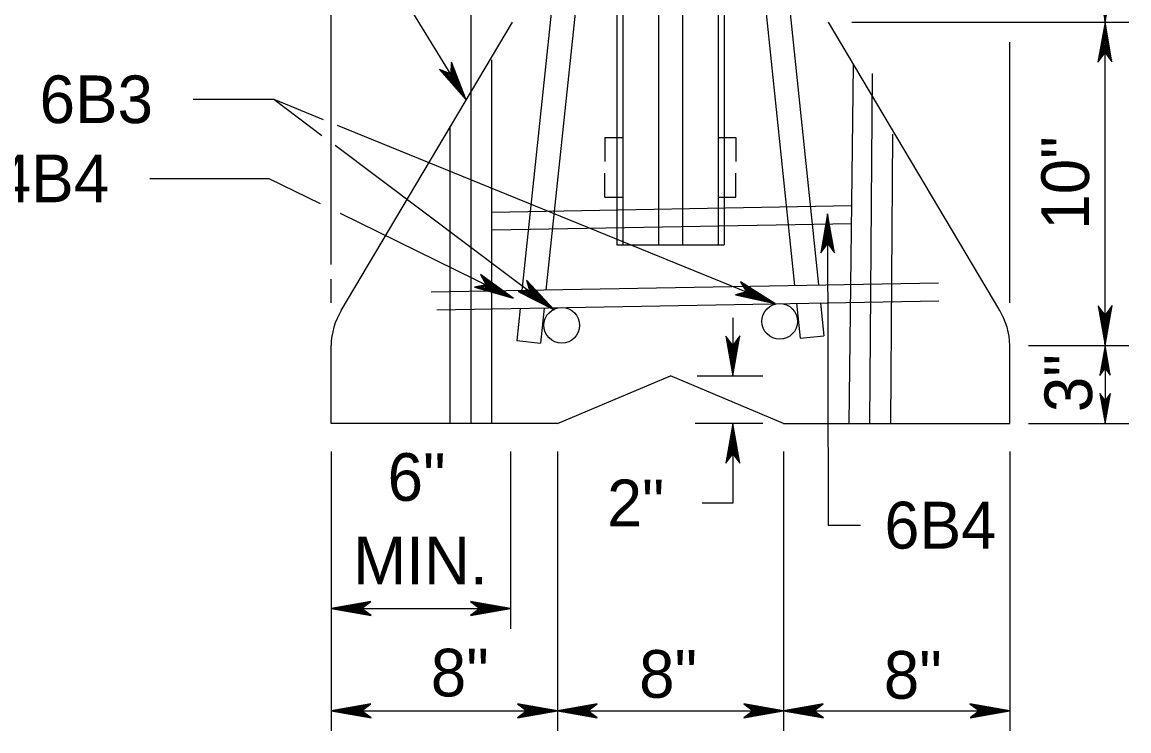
# Model space of a CAD drawing. Extents: x 499866 to 500993, y 499985 to 500645.
# Drawn here: x 500319.6 to 500412.5, y 500301 to 500360.4 of the extents above; entities that cross this region are included whole.
import ezdxf

# ---------------------------------------------------------------- set-up
doc = ezdxf.new("R2010")
doc.units = 0
for name, color, linetype in [('24', 7, 'Continuous'), ('5', 7, 'Continuous'), ('60', 7, 'Continuous')]:
    doc.layers.add(name, color=color, linetype=linetype)

msp = doc.modelspace()

# ---------------------------------------------------------------- linework, layer by layer
at = {"layer": '24'}
for points in [[(500409.949, 500363.769), (500410.532, 500360.436), (500410.527, 500360.658)], [(500410.532, 500360.436), (500411.125, 500363.786)], [(500410.532, 500360.436), (500409.94, 500357.086), (500410.532, 500357.886), (500411.115, 500357.103), (500410.532, 500360.436), (500410.538, 500360.214), (500409.984, 500357.18), (500410.54, 500357.949), (500411.07, 500357.239), (500410.549, 500360.094), (500410.532, 500359.982), (500410.071, 500357.383), (500410.539, 500357.966), (500410.994, 500357.367), (500410.532, 500359.931), (500410.549, 500359.82), (500410.139, 500357.548), (500410.532, 500357.99), (500410.941, 500357.539), (500410.55, 500359.496), (500410.549, 500359.307), (500410.223, 500357.717), (500410.523, 500358.026), (500410.856, 500357.693), (500410.532, 500359.273), (500410.522, 500359.094), (500410.317, 500357.899), (500410.55, 500358.129), (500410.779, 500357.879), (500410.532, 500358.93), (500410.515, 500358.761), (500410.378, 500358.043), (500410.54, 500358.161), (500410.719, 500357.966), (500410.532, 500358.674), (500410.421, 500358.205), (500410.549, 500358.273), (500410.677, 500358.068), (500410.55, 500358.556), (500410.472, 500358.249), (500410.573, 500358.378), (500410.634, 500358.23), (500410.54, 500358.377), (500410.523, 500358.3)], [(500356.927, 500353.917), (500355.679, 500357.082), (500355.594, 500356.09), (500354.687, 500356.452), (500356.927, 500353.917), (500356.805, 500354.103), (500355.691, 500356.979), (500355.62, 500356.033), (500354.797, 500356.361), (500356.734, 500354.2), (500356.689, 500354.304), (500355.724, 500356.76), (500355.629, 500356.018), (500354.928, 500356.291), (500356.663, 500354.347), (500356.591, 500354.433), (500355.752, 500356.584), (500355.648, 500356.002), (500355.063, 500356.173), (500356.421, 500354.709), (500356.323, 500354.87), (500355.768, 500356.396), (500355.675, 500355.976), (500355.216, 500356.086), (500356.319, 500354.908), (500356.234, 500355.066), (500355.783, 500356.192), (500355.705, 500355.874), (500355.38, 500355.967), (500356.139, 500355.2), (500356.066, 500355.353), (500355.807, 500356.037), (500355.731, 500355.852), (500355.476, 500355.925), (500356.006, 500355.419), (500355.855, 500355.876), (500355.782, 500355.751), (500355.565, 500355.86), (500355.929, 500355.51), (500355.834, 500355.812), (500355.815, 500355.65), (500355.686, 500355.744), (500355.844, 500355.668), (500355.818, 500355.742)], [(500387.251, 500344.346), (500386.678, 500341.071), (500387.256, 500341.854), (500387.827, 500341.09), (500387.251, 500344.346), (500387.257, 500344.129), (500386.721, 500341.163), (500387.263, 500341.915), (500387.782, 500341.222), (500387.267, 500344.011), (500387.251, 500343.903), (500386.805, 500341.362), (500387.262, 500341.932), (500387.708, 500341.347), (500387.251, 500343.852), (500387.268, 500343.744), (500386.872, 500341.523), (500387.255, 500341.956), (500387.656, 500341.515), (500387.269, 500343.428), (500387.269, 500343.243), (500386.954, 500341.688), (500387.246, 500341.991), (500387.572, 500341.666), (500387.253, 500343.21), (500387.243, 500343.035), (500387.045, 500341.866), (500387.272, 500342.091), (500387.496, 500341.848), (500387.254, 500342.875), (500387.238, 500342.71), (500387.104, 500342.007), (500387.262, 500342.123), (500387.438, 500341.932), (500387.254, 500342.624), (500387.146, 500342.166), (500387.271, 500342.232), (500387.397, 500342.032), (500387.271, 500342.509), (500387.196, 500342.208), (500387.295, 500342.334), (500387.354, 500342.19), (500387.262, 500342.334), (500387.245, 500342.259)], [(500387.251, 500344.346), (500387.305, 500318.223), (500390.021, 500318.223)], [(500360.871, 500337.262), (500358.124, 500339.269), (500358.582, 500338.385), (500357.622, 500338.207), (500360.871, 500337.262), (500360.668, 500337.355), (500358.189, 500339.189), (500358.635, 500338.351), (500357.763, 500338.188), (500360.556, 500337.399), (500360.463, 500337.462), (500358.333, 500339.022), (500358.65, 500338.344), (500357.912, 500338.199), (500360.417, 500337.485), (500360.31, 500337.519), (500358.451, 500338.888), (500358.675, 500338.34), (500358.09, 500338.172), (500360.019, 500337.661), (500359.85, 500337.745), (500358.565, 500338.738), (500358.711, 500338.332), (500358.265, 500338.18), (500359.827, 500337.775), (500359.671, 500337.863), (500358.687, 500338.573), (500358.792, 500338.263), (500358.467, 500338.167), (500359.519, 500337.926), (500359.375, 500338.015), (500358.79, 500338.455), (500358.825, 500338.258), (500358.571, 500338.183), (500359.289, 500338.039), (500358.917, 500338.345), (500358.922, 500338.2), (500358.68, 500338.175), (500359.176, 500338.075), (500358.933, 500338.28), (500359.005, 500338.132), (500358.845, 500338.143), (500359.019, 500338.163), (500358.957, 500338.212)], [(500364.296, 500336.299), (500361.973, 500338.784), (500362.258, 500337.83), (500361.281, 500337.834), (500364.296, 500336.299), (500364.115, 500336.428), (500362.022, 500338.693), (500362.303, 500337.787), (500361.417, 500337.79), (500364.012, 500336.491), (500363.933, 500336.572), (500362.133, 500338.502), (500362.317, 500337.777), (500361.565, 500337.773), (500363.892, 500336.603), (500363.794, 500336.656), (500362.223, 500338.348), (500362.341, 500337.768), (500361.734, 500337.713), (500363.534, 500336.85), (500363.384, 500336.964), (500362.307, 500338.179), (500362.375, 500337.754), (500361.908, 500337.688), (500363.366, 500336.997), (500363.23, 500337.113), (500362.397, 500337.995), (500362.441, 500337.671), (500362.104, 500337.638), (500363.092, 500337.203), (500362.968, 500337.318), (500362.475, 500337.86), (500362.473, 500337.659), (500362.21, 500337.634), (500362.887, 500337.358), (500362.58, 500337.728), (500362.557, 500337.585), (500362.316, 500337.605), (500362.783, 500337.414), (500362.583, 500337.661), (500362.626, 500337.502), (500362.471, 500337.543), (500362.645, 500337.53), (500362.594, 500337.59)], [(500382.815, 500336.834), (500379.936, 500338.647), (500380.454, 500337.796), (500379.508, 500337.552), (500382.815, 500336.834), (500382.606, 500336.912), (500380.006, 500338.571), (500380.509, 500337.766), (500379.651, 500337.543), (500382.491, 500336.948), (500382.394, 500337.005), (500380.162, 500338.414), (500380.525, 500337.76), (500379.798, 500337.565), (500382.347, 500337.025), (500382.238, 500337.052), (500380.289, 500338.288), (500380.55, 500337.758), (500379.977, 500337.549), (500381.938, 500337.173), (500381.763, 500337.245), (500380.413, 500338.146), (500380.586, 500337.752), (500380.152, 500337.57), (500381.738, 500337.273), (500381.576, 500337.35), (500380.546, 500337.991), (500380.671, 500337.689), (500380.354, 500337.571), (500381.42, 500337.402), (500381.27, 500337.482), (500380.657, 500337.88), (500380.705, 500337.686), (500380.457, 500337.594), (500381.183, 500337.499), (500380.791, 500337.779), (500380.806, 500337.635), (500380.567, 500337.594), (500381.067, 500337.528), (500380.812, 500337.715), (500380.893, 500337.573), (500380.733, 500337.573), (500380.905, 500337.604), (500380.84, 500337.649)], [(500410.532, 500333.301), (500411.125, 500336.651), (500410.532, 500335.851), (500409.949, 500336.634), (500410.532, 500333.301), (500410.527, 500333.524), (500411.081, 500336.557), (500410.525, 500335.788), (500409.995, 500336.499), (500410.516, 500333.644), (500410.532, 500333.755), (500410.994, 500336.354), (500410.526, 500335.771), (500410.071, 500336.37), (500410.533, 500333.806), (500410.516, 500333.918), (500410.926, 500336.189), (500410.533, 500335.747), (500410.124, 500336.198), (500410.515, 500334.241), (500410.516, 500334.43), (500410.842, 500336.021), (500410.542, 500335.711), (500410.209, 500336.045), (500410.532, 500334.464), (500410.543, 500334.643), (500410.748, 500335.839), (500410.515, 500335.609), (500410.286, 500335.858), (500410.532, 500334.807), (500410.55, 500334.976), (500410.687, 500335.694), (500410.525, 500335.576), (500410.346, 500335.771), (500410.533, 500335.063), (500410.644, 500335.532), (500410.516, 500335.464), (500410.387, 500335.67), (500410.515, 500335.181), (500410.593, 500335.489), (500410.491, 500335.36), (500410.431, 500335.508), (500410.525, 500335.361), (500410.542, 500335.437)], [(500379.299, 500330.762), (500379.891, 500334.113), (500379.299, 500333.312), (500378.716, 500334.095), (500379.299, 500330.762), (500379.293, 500330.985), (500379.847, 500334.019), (500379.292, 500333.25), (500378.762, 500333.96), (500379.283, 500331.105), (500379.299, 500331.217), (500379.761, 500333.815), (500379.292, 500333.232), (500378.838, 500333.832), (500379.3, 500331.268), (500379.283, 500331.379), (500379.693, 500333.651), (500379.3, 500333.209), (500378.891, 500333.66), (500379.282, 500331.702), (500379.283, 500331.891), (500379.608, 500333.482), (500379.309, 500333.173), (500378.976, 500333.506), (500379.299, 500331.925), (500379.31, 500332.104), (500379.514, 500333.3), (500379.282, 500333.07), (500379.053, 500333.319), (500379.299, 500332.268), (500379.316, 500332.437), (500379.453, 500333.156), (500379.292, 500333.037), (500379.113, 500333.233), (500379.3, 500332.525), (500379.411, 500332.993), (500379.283, 500332.925), (500379.154, 500333.131), (500379.282, 500332.642), (500379.359, 500332.95), (500379.258, 500332.821), (500379.198, 500332.969), (500379.292, 500332.822), (500379.309, 500332.899)], [(500410.532, 500333.301), (500410.088, 500330.789), (500410.532, 500331.389), (500410.97, 500330.802), (500410.532, 500333.301), (500410.537, 500333.135), (500410.121, 500330.859), (500410.538, 500331.436), (500410.935, 500330.903), (500410.545, 500333.044), (500410.532, 500332.961), (500410.186, 500331.011), (500410.538, 500331.449), (500410.879, 500330.999), (500410.532, 500332.922), (500410.545, 500332.839), (500410.237, 500331.135), (500410.532, 500331.467), (500410.839, 500331.128), (500410.545, 500332.596), (500410.545, 500332.454), (500410.301, 500331.261), (500410.525, 500331.493), (500410.775, 500331.243), (500410.532, 500332.429), (500410.525, 500332.295), (500410.371, 500331.398), (500410.545, 500331.571), (500410.717, 500331.384), (500410.532, 500332.172), (500410.52, 500332.045), (500410.417, 500331.507), (500410.538, 500331.595), (500410.672, 500331.448), (500410.532, 500331.98), (500410.449, 500331.628), (500410.545, 500331.679), (500410.641, 500331.525), (500410.545, 500331.891), (500410.488, 500331.661), (500410.563, 500331.757), (500410.609, 500331.646), (500410.538, 500331.757), (500410.525, 500331.699)], [(500410.532, 500326.765), (500410.977, 500329.278), (500410.532, 500328.677), (500410.095, 500329.265), (500410.532, 500326.765), (500410.528, 500326.932), (500410.944, 500329.208), (500410.527, 500328.631), (500410.13, 500329.163), (500410.52, 500327.022), (500410.532, 500327.106), (500410.879, 500329.055), (500410.527, 500328.618), (500410.186, 500329.067), (500410.533, 500327.144), (500410.52, 500327.228), (500410.828, 500328.931), (500410.533, 500328.6), (500410.226, 500328.938), (500410.52, 500327.47), (500410.52, 500327.612), (500410.764, 500328.805), (500410.54, 500328.573), (500410.29, 500328.823), (500410.532, 500327.637), (500410.54, 500327.772), (500410.694, 500328.669), (500410.52, 500328.496), (500410.348, 500328.683), (500410.532, 500327.895), (500410.545, 500328.021), (500410.648, 500328.56), (500410.527, 500328.471), (500410.393, 500328.618), (500410.533, 500328.087), (500410.616, 500328.438), (500410.52, 500328.387), (500410.424, 500328.542), (500410.52, 500328.175), (500410.577, 500328.406), (500410.502, 500328.309), (500410.456, 500328.42), (500410.527, 500328.31), (500410.54, 500328.367)], [(500379.299, 500326.765), (500378.707, 500323.415), (500379.299, 500324.216), (500379.882, 500323.433), (500379.299, 500326.765), (500379.305, 500326.543), (500378.751, 500323.509), (500379.306, 500324.278), (500379.836, 500323.568), (500379.316, 500326.423), (500379.299, 500326.311), (500378.837, 500323.713), (500379.306, 500324.296), (500379.761, 500323.696), (500379.299, 500326.26), (500379.316, 500326.149), (500378.906, 500323.877), (500379.299, 500324.319), (500379.708, 500323.868), (500379.316, 500325.825), (500379.316, 500325.636), (500378.99, 500324.046), (500379.29, 500324.355), (500379.623, 500324.022), (500379.299, 500325.603), (500379.289, 500325.424), (500379.084, 500324.228), (500379.316, 500324.458), (500379.545, 500324.209), (500379.299, 500325.26), (500379.282, 500325.091), (500379.145, 500324.372), (500379.306, 500324.491), (500379.485, 500324.295), (500379.299, 500325.003), (500379.188, 500324.535), (500379.316, 500324.603), (500379.444, 500324.397), (500379.316, 500324.885), (500379.239, 500324.578), (500379.34, 500324.707), (500379.401, 500324.559), (500379.306, 500324.706), (500379.29, 500324.629)], [(500345.582, 500311.227), (500348.932, 500310.635), (500348.132, 500311.227), (500348.915, 500311.81), (500345.582, 500311.227), (500345.804, 500311.233), (500348.838, 500310.679), (500348.069, 500311.234), (500348.78, 500311.764), (500345.925, 500311.243), (500346.036, 500311.227), (500348.635, 500310.765), (500348.052, 500311.234), (500348.651, 500311.689), (500346.087, 500311.227), (500346.198, 500311.243), (500348.47, 500310.833), (500348.028, 500311.227), (500348.479, 500311.635), (500346.522, 500311.244), (500346.711, 500311.243), (500348.302, 500310.918), (500347.992, 500311.218), (500348.325, 500311.551), (500346.745, 500311.227), (500346.924, 500311.217), (500348.119, 500311.012), (500347.889, 500311.244), (500348.139, 500311.473), (500347.088, 500311.227), (500347.257, 500311.21), (500347.975, 500311.073), (500347.857, 500311.234), (500348.052, 500311.413), (500347.344, 500311.227), (500347.813, 500311.115), (500347.745, 500311.243), (500347.95, 500311.372), (500347.462, 500311.244), (500347.769, 500311.167), (500347.64, 500311.268), (500347.788, 500311.328), (500347.641, 500311.234), (500347.718, 500311.218)], [(500360.621, 500311.227), (500357.271, 500311.819), (500358.072, 500311.227), (500357.289, 500310.644), (500360.621, 500311.227), (500360.399, 500311.221), (500357.365, 500311.775), (500358.134, 500311.22), (500357.424, 500310.69), (500360.279, 500311.211), (500360.167, 500311.227), (500357.569, 500311.689), (500358.152, 500311.22), (500357.552, 500310.765), (500360.116, 500311.227), (500360.005, 500311.211), (500357.733, 500311.621), (500358.175, 500311.227), (500357.724, 500310.819), (500359.681, 500311.21), (500359.492, 500311.211), (500357.902, 500311.536), (500358.211, 500311.237), (500357.878, 500310.904), (500359.459, 500311.227), (500359.28, 500311.238), (500358.084, 500311.442), (500358.314, 500311.21), (500358.065, 500310.981), (500359.115, 500311.227), (500358.947, 500311.244), (500358.228, 500311.381), (500358.347, 500311.22), (500358.151, 500311.041), (500358.859, 500311.227), (500358.391, 500311.339), (500358.459, 500311.211), (500358.253, 500311.082), (500358.741, 500311.21), (500358.434, 500311.287), (500358.563, 500311.186), (500358.415, 500311.126), (500358.562, 500311.22), (500358.485, 500311.237)], [(500345.582, 500302.645), (500348.932, 500302.053), (500348.132, 500302.645), (500348.915, 500303.228), (500345.582, 500302.645), (500345.804, 500302.651), (500348.838, 500302.097), (500348.069, 500302.652), (500348.78, 500303.182), (500345.925, 500302.661), (500346.036, 500302.645), (500348.635, 500302.183), (500348.052, 500302.652), (500348.651, 500303.107), (500346.087, 500302.645), (500346.198, 500302.661), (500348.47, 500302.251), (500348.028, 500302.645), (500348.479, 500303.053), (500346.522, 500302.662), (500346.711, 500302.661), (500348.302, 500302.336), (500347.992, 500302.635), (500348.325, 500302.969), (500346.745, 500302.645), (500346.924, 500302.635), (500348.119, 500302.43), (500347.889, 500302.662), (500348.139, 500302.891), (500347.088, 500302.645), (500347.257, 500302.628), (500347.975, 500302.491), (500347.857, 500302.652), (500348.052, 500302.831), (500347.344, 500302.645), (500347.813, 500302.533), (500347.745, 500302.661), (500347.95, 500302.79), (500347.462, 500302.662), (500347.769, 500302.585), (500347.64, 500302.686), (500347.788, 500302.746), (500347.641, 500302.652), (500347.718, 500302.635)], [(500364.568, 500302.645), (500361.218, 500303.237), (500362.018, 500302.645), (500361.235, 500302.062), (500364.568, 500302.645), (500364.345, 500302.639), (500361.311, 500303.193), (500362.08, 500302.638), (500361.37, 500302.108), (500364.225, 500302.629), (500364.114, 500302.645), (500361.515, 500303.107), (500362.098, 500302.638), (500361.498, 500302.183), (500364.062, 500302.645), (500363.951, 500302.629), (500361.679, 500303.039), (500362.121, 500302.645), (500361.67, 500302.237), (500363.628, 500302.628), (500363.439, 500302.629), (500361.848, 500302.954), (500362.157, 500302.655), (500361.824, 500302.322), (500363.405, 500302.645), (500363.226, 500302.656), (500362.03, 500302.86), (500362.26, 500302.628), (500362.011, 500302.399), (500363.062, 500302.645), (500362.893, 500302.662), (500362.175, 500302.799), (500362.293, 500302.638), (500362.097, 500302.459), (500362.805, 500302.645), (500362.337, 500302.757), (500362.405, 500302.629), (500362.199, 500302.5), (500362.688, 500302.628), (500362.38, 500302.705), (500362.509, 500302.604), (500362.361, 500302.544), (500362.508, 500302.638), (500362.431, 500302.655)], [(500364.568, 500302.645), (500367.918, 500302.053), (500367.117, 500302.645), (500367.9, 500303.228), (500364.568, 500302.645), (500364.79, 500302.651), (500367.824, 500302.097), (500367.055, 500302.652), (500367.765, 500303.182), (500364.91, 500302.661), (500365.022, 500302.645), (500367.62, 500302.183), (500367.037, 500302.652), (500367.637, 500303.107), (500365.073, 500302.645), (500365.184, 500302.661), (500367.456, 500302.251), (500367.014, 500302.645), (500367.465, 500303.053), (500365.508, 500302.662), (500365.697, 500302.661), (500367.287, 500302.336), (500366.978, 500302.635), (500367.311, 500302.969), (500365.73, 500302.645), (500365.909, 500302.635), (500367.105, 500302.43), (500366.875, 500302.662), (500367.124, 500302.891), (500366.073, 500302.645), (500366.242, 500302.628), (500366.961, 500302.491), (500366.842, 500302.652), (500367.038, 500302.831), (500366.33, 500302.645), (500366.798, 500302.533), (500366.73, 500302.661), (500366.936, 500302.79), (500366.448, 500302.662), (500366.755, 500302.585), (500366.626, 500302.686), (500366.774, 500302.746), (500366.627, 500302.652), (500366.704, 500302.635)], [(500383.553, 500302.645), (500380.203, 500303.237), (500381.003, 500302.645), (500380.22, 500302.062), (500383.553, 500302.645), (500383.33, 500302.639), (500380.297, 500303.193), (500381.066, 500302.638), (500380.355, 500302.108), (500383.21, 500302.629), (500383.099, 500302.645), (500380.5, 500303.107), (500381.083, 500302.638), (500380.484, 500302.183), (500383.048, 500302.645), (500382.936, 500302.629), (500380.665, 500303.039), (500381.107, 500302.645), (500380.656, 500302.237), (500382.613, 500302.628), (500382.424, 500302.629), (500380.833, 500302.954), (500381.143, 500302.655), (500380.809, 500302.322), (500382.39, 500302.645), (500382.211, 500302.656), (500381.015, 500302.86), (500381.245, 500302.628), (500380.996, 500302.399), (500382.047, 500302.645), (500381.878, 500302.662), (500381.16, 500302.799), (500381.278, 500302.638), (500381.083, 500302.459), (500381.791, 500302.645), (500381.322, 500302.757), (500381.39, 500302.629), (500381.184, 500302.5), (500381.673, 500302.628), (500381.365, 500302.705), (500381.494, 500302.604), (500381.346, 500302.544), (500381.493, 500302.638), (500381.417, 500302.655)], [(500383.553, 500302.645), (500386.903, 500302.053), (500386.102, 500302.645), (500386.885, 500303.228), (500383.553, 500302.645), (500383.775, 500302.651), (500386.809, 500302.097), (500386.04, 500302.652), (500386.75, 500303.182), (500383.895, 500302.661), (500384.007, 500302.645), (500386.606, 500302.183), (500386.023, 500302.652), (500386.622, 500303.107), (500384.058, 500302.645), (500384.169, 500302.661), (500386.441, 500302.251), (500385.999, 500302.645), (500386.45, 500303.053), (500384.493, 500302.662), (500384.682, 500302.661), (500386.272, 500302.336), (500385.963, 500302.635), (500386.296, 500302.969), (500384.716, 500302.645), (500384.894, 500302.635), (500386.09, 500302.43), (500385.86, 500302.662), (500386.11, 500302.891), (500385.059, 500302.645), (500385.227, 500302.628), (500385.946, 500302.491), (500385.827, 500302.652), (500386.023, 500302.831), (500385.315, 500302.645), (500385.783, 500302.533), (500385.716, 500302.661), (500385.921, 500302.79), (500385.433, 500302.662), (500385.74, 500302.585), (500385.611, 500302.686), (500385.759, 500302.746), (500385.612, 500302.652), (500385.689, 500302.635)], [(500402.539, 500302.645), (500399.189, 500303.237), (500399.989, 500302.645), (500399.206, 500302.062), (500402.539, 500302.645), (500402.316, 500302.639), (500399.282, 500303.193), (500400.052, 500302.638), (500399.341, 500302.108), (500402.196, 500302.629), (500402.085, 500302.645), (500399.486, 500303.107), (500400.069, 500302.638), (500399.469, 500302.183), (500402.033, 500302.645), (500401.922, 500302.629), (500399.651, 500303.039), (500400.093, 500302.645), (500399.641, 500302.237), (500401.599, 500302.628), (500401.41, 500302.629), (500399.819, 500302.954), (500400.129, 500302.655), (500399.795, 500302.322), (500401.376, 500302.645), (500401.197, 500302.656), (500400.001, 500302.86), (500400.231, 500302.628), (500399.982, 500302.399), (500401.033, 500302.645), (500400.864, 500302.662), (500400.146, 500302.799), (500400.264, 500302.638), (500400.069, 500302.459), (500400.777, 500302.645), (500400.308, 500302.757), (500400.376, 500302.629), (500400.17, 500302.5), (500400.659, 500302.628), (500400.351, 500302.705), (500400.48, 500302.604), (500400.332, 500302.544), (500400.479, 500302.638), (500400.403, 500302.655)]]:
    msp.add_lwpolyline(points, dxfattribs=at)
at = {"layer": '5'}
for p, q in [((500410.532, 500360.436), (500410.532, 500408.703)), ((500367.837, 500397.193), (500361.595, 500337.912)), ((500380.327, 500397.193), (500386.48, 500338.379)), ((500378.371, 500396.902), (500384.478, 500338.327)), ((500370.063, 500391.629), (500370.063, 500341.754)), ((500373.061, 500391.629), (500373.061, 500341.754)), ((500375.06, 500391.66), (500375.06, 500341.754)), ((500378.057, 500391.66), (500378.057, 500341.754)), ((500378.557, 500391.66), (500378.557, 500341.754)), ((500368.189, 500381.281), (500363.607, 500337.933)), ((500369.564, 500380.588), (500369.564, 500341.754)), ((500357.323, 500326.765), (500357.323, 500379.722)), ((500345.582, 500340.097), (500345.582, 500368.682)), ((500346.432, 500336.241), (500360.798, 500360.436)), ((500401.688, 500336.241), (500387.323, 500360.436)), ((500389.288, 500360.436), (500412.531, 500360.436)), ((500410.532, 500333.301), (500410.532, 500360.436)), ((500402.539, 500336.88), (500402.539, 500358.744)), ((500359.072, 500326.765), (500359.072, 500357.272)), ((500389.049, 500326.765), (500389.434, 500356.858)), ((500390.797, 500326.779), (500391.015, 500356.133)), ((500340.783, 500353.961), (500344.811, 500350.936)), ((500346.1, 500351.795), (500382.815, 500336.834)), ((500355.574, 500326.765), (500355.574, 500351.702)), ((500368.564, 500350.747), (500368.564, 500348.749)), ((500368.564, 500350.747), (500370.063, 500350.747)), ((500378.057, 500350.747), (500379.556, 500350.747)), ((500379.556, 500350.747), (500379.556, 500348.749)), ((500392.546, 500326.765), (500392.726, 500351.043)), ((500345.914, 500350.107), (500364.296, 500336.299)), ((500368.564, 500345.751), (500368.564, 500347.749)), ((500379.556, 500345.751), (500379.556, 500347.749)), ((500368.564, 500345.751), (500370.063, 500345.751)), ((500378.057, 500345.751), (500379.556, 500345.751)), ((500346.335, 500344.392), (500360.871, 500337.262)), ((500359.072, 500344.503), (500389.261, 500345.039)), ((500359.098, 500343.005), (500389.288, 500343.54)), ((500369.564, 500341.754), (500378.557, 500341.754)), ((500345.582, 500336.88), (500345.582, 500338.88)), ((500353.985, 500337.797), (500396.558, 500338.553)), ((500354.445, 500336.306), (500396.585, 500337.054)), ((500384.633, 500336.839), (500384.939, 500333.905)), ((500386.639, 500336.864), (500386.927, 500334.113)), ((500361.436, 500336.397), (500361.153, 500333.712)), ((500363.448, 500336.423), (500363.139, 500333.502)), ((500379.299, 500335.619), (500379.299, 500330.762)), ((500384.939, 500333.905), (500386.927, 500334.113)), ((500345.582, 500326.765), (500345.582, 500333.301)), ((500361.152, 500333.712), (500363.139, 500333.502)), ((500402.539, 500326.765), (500402.539, 500333.301)), ((500404.12, 500333.301), (500412.531, 500333.301)), ((500410.532, 500333.301), (500410.532, 500326.765)), ((500364.568, 500326.765), (500374.06, 500330.762)), ((500383.553, 500326.765), (500374.06, 500330.762)), ((500376.293, 500330.762), (500381.798, 500330.762)), ((500364.568, 500326.765), (500345.582, 500326.765)), ((500381.798, 500326.765), (500376.141, 500326.765)), ((500383.553, 500326.765), (500402.539, 500326.765)), ((500404.12, 500326.765), (500412.531, 500326.765)), ((500345.582, 500324.399), (500345.582, 500300.962)), ((500360.621, 500324.399), (500360.621, 500309.536)), ((500364.568, 500324.399), (500364.568, 500300.962)), ((500383.553, 500324.399), (500383.553, 500300.962)), ((500402.539, 500324.399), (500402.539, 500300.962)), ((500345.582, 500311.227), (500360.621, 500311.227)), ((500345.582, 500302.645), (500364.568, 500302.645)), ((500364.568, 500302.645), (500383.553, 500302.645)), ((500383.553, 500302.645), (500402.539, 500302.645))]:
    msp.add_line(p, q, dxfattribs=at)
for points in [[(500322.942, 500375.549), (500343.653, 500375.549), (500356.927, 500353.917)], [(500333.995, 500353.961), (500340.783, 500353.961), (500344.922, 500352.275)], [(500330.363, 500347.324), (500340.356, 500347.324), (500344.667, 500345.21)], [(500379.299, 500326.765), (500379.299, 500320.081), (500376.713, 500320.081)]]:
    msp.add_lwpolyline(points, dxfattribs=at)
for centre, start, end in [((500351.563, 500333.14), 148.85817, 178.45857), ((500396.557, 500333.14), 1.54143, 31.14183)]:
    msp.add_arc(centre, 5.995, start, end, dxfattribs=at)
at = {"layer": '60'}
for centre in [(500383.226, 500335.327), (500364.938, 500334.994)]:
    msp.add_circle(centre, 1.499, dxfattribs=at)

# ---------------------------------------------------------------- texts
at = {"layer": '5'}
for s, height, p in [('6B3', 4, (500321.113, 500351.961)), ('4B4', 4, (500317.438, 500345.324)), ('6"', 4, (500350.318, 500320.265)), ('2"', 3.937, (500368.744, 500318.113)), ('6B4', 3.937, (500392.021, 500316.255)), ('MIN.', 4, (500347.428, 500313.265)), ('8"', 4, (500353.945, 500303.851)), ('8"', 4, (500371.426, 500303.739)), ('8"', 4, (500391.965, 500303.66))]:
    msp.add_text(s, height=height, dxfattribs=at).set_placement(p)
for s, p in [('10"', (500409.187, 500343.012)), ('3"', (500409.448, 500327.708))]:
    msp.add_text(s, height=4, rotation=90, dxfattribs=at).set_placement(p)

doc.saveas('drawing.dxf')
